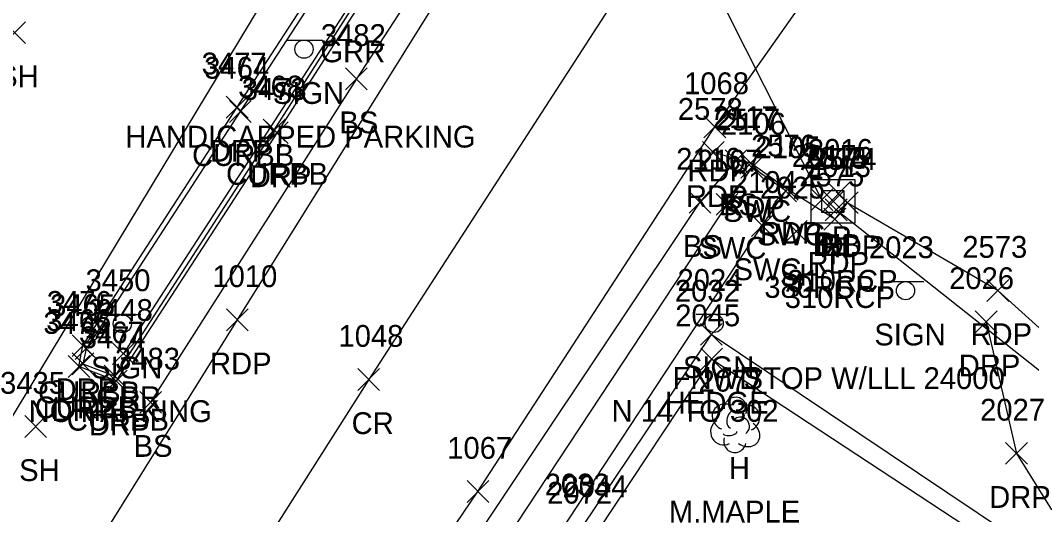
# Model space of a CAD drawing. Extents: x 1634209 to 1639641, y 608564 to 612258.
# Drawn here: x 1639060.6 to 1639153.3, y 611205.4 to 611250.8 of the extents above; entities that cross this region are included whole.
import ezdxf

# ---------------------------------------------------------------- set-up
doc = ezdxf.new("R2010")
doc.units = 0
for name, color, linetype in [('D_A', 7, 'Continuous'), ('D_C', 7, 'Continuous'), ('D_I', 7, 'Continuous'), ('D_TIC', 7, 'Continuous'), ('DCP', 7, 'Continuous'), ('DS', 7, 'Continuous'), ('L_A', 7, 'Continuous'), ('L_C', 7, 'Continuous'), ('L_I', 7, 'Continuous'), ('L_TIC', 7, 'Continuous'), ('LAHR', 7, 'Continuous'), ('LELB', 7, 'Continuous'), ('LFNC', 7, 'Continuous'), ('LTD', 7, 'Continuous'), ('P_A', 7, 'Continuous'), ('P_I', 7, 'Continuous'), ('P_TIC', 7, 'Continuous'), ('PET', 7, 'Continuous'), ('PRC', 7, 'Continuous'), ('R_A', 7, 'Continuous'), ('R_I', 7, 'Continuous'), ('R_TIC', 7, 'Continuous'), ('RC', 7, 'Continuous'), ('RDP', 7, 'Continuous'), ('RGR', 7, 'Continuous'), ('RSW', 7, 'Continuous'), ('S_A', 7, 'Continuous'), ('S_C', 7, 'Continuous'), ('S_I', 7, 'Continuous'), ('SSGN', 7, 'Continuous')]:
    doc.layers.add(name, color=color, linetype=linetype)

msp = doc.modelspace()

# ---------------------------------------------------------------- linework, layer by layer
at = {"layer": 'D_TIC'}
for points in [[(1639134.631, 611233.883), (1639136.631, 611235.883)], [(1639136.631, 611233.883), (1639134.631, 611235.883)], [(1639133.093, 611233.316), (1639135.093, 611235.316)], [(1639135.093, 611233.316), (1639133.093, 611235.316)], [(1639134.136, 611233.162), (1639136.136, 611235.162)], [(1639136.136, 611233.162), (1639134.136, 611235.162)], [(1639134.4, 611232.388), (1639136.4, 611234.388)], [(1639136.4, 611232.388), (1639134.4, 611234.388)]]:
    msp.add_lwpolyline(points, dxfattribs=at)
at = {"layer": 'DCP'}
for points in [[(1639053.212, 611203.404), (1639105.209, 611289.55)], [(1639134.093, 611234.316), (1639106.078, 611289.886)], [(1639159.896, 611213.983), (1639135.4, 611233.388)]]:
    msp.add_lwpolyline(points, dxfattribs=at)
at = {"layer": 'DS'}
for p, q in [((1639133.093, 611236.155), (1639137.093, 611236.155)), ((1639133.093, 611232.155), (1639133.093, 611236.155)), ((1639137.093, 611236.155), (1639137.093, 611232.155)), ((1639134.093, 611233.155), (1639134.093, 611235.155)), ((1639134.093, 611235.155), (1639136.093, 611235.155)), ((1639136.093, 611235.155), (1639136.093, 611233.155)), ((1639135.098, 611234.157), (1639135.098, 611234.157)), ((1639135.098, 611234.157), (1639135.098, 611234.157)), ((1639136.093, 611233.155), (1639134.093, 611233.155)), ((1639137.093, 611232.155), (1639133.093, 611232.155))]:
    msp.add_line(p, q, dxfattribs=at)
at = {"layer": 'L_TIC'}
for points in [[(1639059.097, 611248.624), (1639061.097, 611250.624)], [(1639061.097, 611248.624), (1639059.097, 611250.624)], [(1639090.422, 611244.404), (1639092.422, 611246.404)], [(1639092.422, 611244.404), (1639090.422, 611246.404)], [(1639125.22, 611236.882), (1639127.22, 611238.882)], [(1639127.22, 611236.882), (1639125.22, 611238.882)], [(1639121.911, 611233.067), (1639123.911, 611235.067)], [(1639123.911, 611233.067), (1639121.911, 611235.067)], [(1639130.75, 611230.422), (1639132.75, 611232.422)], [(1639132.75, 611230.422), (1639130.75, 611232.422)], [(1639122.947, 611220.972), (1639124.947, 611222.972)], [(1639124.947, 611220.972), (1639122.947, 611222.972)], [(1639122.989, 611218.711), (1639124.989, 611220.711)], [(1639124.989, 611218.711), (1639122.989, 611220.711)], [(1639071.56, 611214.741), (1639073.56, 611216.741)], [(1639073.56, 611214.741), (1639071.56, 611216.741)], [(1639061.02, 611212.522), (1639063.02, 611214.522)], [(1639063.02, 611212.522), (1639061.02, 611214.522)]]:
    msp.add_lwpolyline(points, dxfattribs=at)
at = {"layer": 'LAHR'}
msp.add_lwpolyline([(1639113.651, 611204.037), (1639123.989, 611219.711), (1639156.206, 611198.515)], dxfattribs=at)
at = {"layer": 'LELB'}
for points in [[(1639113.243, 611281.921), (1639107.569, 611270.212), (1639091.422, 611245.404), (1639072.56, 611215.741)], [(1639041.81, 611107.811), (1639056.236, 611130.355), (1639075.108, 611160.999), (1639098.499, 611197.466), (1639122.911, 611234.067), (1639126.22, 611237.882)]]:
    msp.add_lwpolyline(points, dxfattribs=at)
at = {"layer": 'LFNC'}
msp.add_lwpolyline([(1639155.815, 611192.801), (1639159.249, 611198.276), (1639123.947, 611221.972), (1639112.019, 611204.198)], dxfattribs=at)
at = {"layer": 'LTD'}
msp.add_line((1639126.125, 611213.72), (1639126.125, 611213.72), dxfattribs=at)
msp.add_line((1639126.125, 611213.72), (1639126.125, 611213.72), dxfattribs=at)
msp.add_arc((1639126.172, 611215.154), 1.047, 335.52715, 180.95627, dxfattribs=at)
for centre, major_axis, ratio, start_param, end_param in [((1639125.333, 611214.386), (1.21, -0.512), 0.895232, 1.570796, 4.712389), ((1639127.167, 611214.303), (-1.141, -0.483), 0.949671, 1.570796, 4.712389), ((1639125.917, 611214.178), (-0.208, -0.792), 0.645439, 3.141593, 6.283185), ((1639126.625, 611213.553), (-0.5, 0.667), 0.989748, 3.141593, 6.283185), ((1639125.042, 611213.011), (0.584, -1.042), 0.959034, 3.141593, 6.283185), ((1639127.125, 611212.886), (-1.09, 0.792), 0.841452, 1.570796, 4.712389), ((1639126.125, 611212.22), (0.265, 1.061), 0.942809, 1.570796, 4.712389), ((1639125.667, 611212.969), (-0.625, -0.083), 0.423636, 0, 3.141593)]:
    msp.add_ellipse(centre, major_axis=major_axis, ratio=ratio, start_param=start_param, end_param=end_param, dxfattribs=at)
at = {"layer": 'P_TIC'}
for points in [[(1639123.272, 611239.99), (1639125.272, 611241.99)], [(1639125.272, 611239.99), (1639123.272, 611241.99)], [(1639123.139, 611237.638), (1639125.139, 611239.638)], [(1639125.139, 611237.638), (1639123.139, 611239.638)], [(1639126.562, 611236.663), (1639128.562, 611238.663)], [(1639128.562, 611236.663), (1639126.562, 611238.663)], [(1639129.918, 611234.275), (1639131.918, 611236.275)], [(1639131.918, 611234.275), (1639129.918, 611236.275)], [(1639135.405, 611233.042), (1639137.405, 611235.042)], [(1639137.405, 611233.042), (1639135.405, 611235.042)], [(1639134.28, 611231.533), (1639136.28, 611233.533)], [(1639136.28, 611231.533), (1639134.28, 611233.533)], [(1639149.219, 611224.989), (1639151.219, 611226.989)], [(1639151.219, 611224.989), (1639149.219, 611226.989)], [(1639079.513, 611222.302), (1639081.513, 611224.302)], [(1639081.513, 611222.302), (1639079.513, 611224.302)], [(1639091.552, 611216.828), (1639093.552, 611218.828)], [(1639093.552, 611216.828), (1639091.552, 611218.828)], [(1639101.566, 611206.561), (1639103.566, 611208.561)], [(1639103.566, 611206.561), (1639101.566, 611208.561)]]:
    msp.add_lwpolyline(points, dxfattribs=at)
at = {"layer": 'PET'}
for points in [[(1638854.828, 610853.218), (1638885.372, 610909), (1638902.819, 610937.282), (1638929.331, 610982.561), (1638950.918, 611019.419), (1638971.285, 611051.917), (1639000.041, 611096.961), (1639023.569, 611133.699), (1639039.122, 611159.191), (1639064.624, 611197.785), (1639080.513, 611223.302), (1639114.226, 611277.337), (1639131.174, 611302.276), (1639149.638, 611331.789), (1639176.419, 611372.354), (1639193.482, 611398.877), (1639220.957, 611441.468), (1639247.215, 611483.75)], [(1638878.405, 610839.817), (1638902.262, 610883.101), (1638925.756, 610925.063), (1638957.254, 610978.118), (1638978.727, 611014.117), (1639004.294, 611055.324), (1639040.966, 611112.282), (1639073.406, 611162.89), (1639072.716, 611163.464), (1639102.566, 611207.561), (1639124.272, 611240.99), (1639140.685, 611264.292), (1639156.198, 611287.398), (1639175.63, 611318.102), (1639189.772, 611341.609), (1639219.882, 611389.38), (1639245.262, 611428.037), (1639265.275, 611462.646)], [(1639410.825, 610892.364), (1639390.458, 610919.541), (1639371.801, 610946.358), (1639349.879, 610975.696), (1639327.189, 611005.386), (1639302.754, 611038.38), (1639275.028, 611075.512), (1639248.834, 611108.817), (1639223.626, 611142.441), (1639205.296, 611166.276), (1639182.184, 611194.122), (1639165.678, 611212.038), (1639150.219, 611225.989), (1639136.405, 611234.042), (1639135.28, 611232.533), (1639130.918, 611235.275), (1639127.562, 611237.663), (1639124.139, 611238.638)]]:
    msp.add_lwpolyline(points, dxfattribs=at)
at = {"layer": 'PRC'}
msp.add_lwpolyline([(1639250.459, 611462.838), (1639222.36, 611418.184), (1639195.342, 611376.275), (1639169.71, 611336.75), (1639147.167, 611302.779), (1639120.589, 611261.162), (1639092.552, 611217.828), (1639063.709, 611172.415), (1639032.458, 611123.696), (1639004.791, 611080.304), (1638977.88, 611037.269), (1638950.436, 610992.128), (1638925.956, 610950.29), (1638900.285, 610905.363), (1638879.746, 610869.196), (1638867.145, 610846.082)], dxfattribs=at)
at = {"layer": 'R_TIC'}
for points in [[(1639079.495, 611241.8), (1639081.495, 611243.8)], [(1639081.495, 611241.8), (1639079.495, 611243.8)], [(1639079.778, 611241.409), (1639081.778, 611243.409)], [(1639081.778, 611241.409), (1639079.778, 611243.409)], [(1639082.889, 611239.687), (1639084.889, 611241.687)], [(1639084.889, 611239.687), (1639082.889, 611241.687)], [(1639083.165, 611239.463), (1639085.165, 611241.463)], [(1639085.165, 611239.463), (1639083.165, 611241.463)], [(1639126.669, 611236.284), (1639128.669, 611238.284)], [(1639128.669, 611236.284), (1639126.669, 611238.284)], [(1639129.776, 611234.122), (1639131.776, 611236.122)], [(1639131.776, 611234.122), (1639129.776, 611236.122)], [(1639124.395, 611232.898), (1639126.395, 611234.898)], [(1639126.395, 611232.898), (1639124.395, 611234.898)], [(1639127.622, 611230.936), (1639129.622, 611232.936)], [(1639129.622, 611230.936), (1639127.622, 611232.936)], [(1639148.147, 611222.119), (1639150.147, 611224.119)], [(1639150.147, 611222.119), (1639148.147, 611224.119)], [(1639065.357, 611219.94), (1639067.357, 611221.94)], [(1639067.357, 611219.94), (1639065.357, 611221.94)], [(1639065.652, 611219.653), (1639067.652, 611221.653)], [(1639067.652, 611219.653), (1639065.652, 611221.653)], [(1639069.072, 611219.203), (1639071.072, 611221.203)], [(1639071.072, 611219.203), (1639069.072, 611221.203)], [(1639064.987, 611218.018), (1639066.987, 611220.018)], [(1639066.987, 611218.018), (1639064.987, 611220.018)], [(1639065.359, 611218.274), (1639067.359, 611220.274)], [(1639067.359, 611218.274), (1639065.359, 611220.274)], [(1639068.295, 611217.144), (1639070.295, 611219.144)], [(1639070.295, 611217.144), (1639068.295, 611219.144)], [(1639068.408, 611216.699), (1639070.408, 611218.699)], [(1639070.408, 611216.699), (1639068.408, 611218.699)], [(1639150.93, 611210.062), (1639152.93, 611212.062)], [(1639152.93, 611210.062), (1639150.93, 611212.062)]]:
    msp.add_lwpolyline(points, dxfattribs=at)
at = {"layer": 'RC'}
msp.add_lwpolyline([(1639104.858, 611279.429), (1639092.734, 611260.844), (1639080.778, 611242.409), (1639066.652, 611220.653), (1639066.359, 611219.274), (1639069.295, 611218.144), (1639083.889, 611240.687), (1639098.149, 611263.05), (1639106.115, 611275.731)], dxfattribs=at)
at = {"layer": 'RDP'}
for points in [[(1639106.497, 611275.321), (1639098.464, 611262.727), (1639084.165, 611240.463), (1639069.408, 611217.699), (1639065.987, 611219.018), (1639066.357, 611220.94), (1639080.495, 611242.8), (1639092.355, 611261.077), (1639105.006, 611280.566)], [(1639149.147, 611223.119), (1639151.93, 611211.062), (1639160.002, 611198.081), (1639156.164, 611192.928)]]:
    msp.add_lwpolyline(points, dxfattribs=at)
at = {"layer": 'RGR'}
msp.add_lwpolyline([(1639105.677, 611275.426), (1639090.632, 611251.917), (1639070.072, 611220.203)], dxfattribs=at)
at = {"layer": 'RSW'}
msp.add_lwpolyline([(1639046.008, 611105.024), (1639061.85, 611129.552), (1639078.572, 611155.899), (1639101.994, 611191.521), (1639128.622, 611231.936), (1639130.776, 611235.122), (1639127.669, 611237.284), (1639125.395, 611233.898), (1639098.324, 611192.857), (1639074.538, 611156.78), (1639058.008, 611130.674), (1639042.924, 611107.097)], dxfattribs=at)
at = {"layer": 'SSGN'}
for p, q in [((1639084.971, 611248.952), (1639088.305, 611248.952)), ((1639086.618, 611248.119), (1639086.618, 611248.119)), ((1639140.111, 611226.808), (1639143.445, 611226.808)), ((1639141.758, 611225.975), (1639141.758, 611225.975)), ((1639068.316, 611223.783), (1639071.649, 611223.783)), ((1639122.567, 611223.814), (1639125.9, 611223.814)), ((1639069.963, 611222.95), (1639069.963, 611222.95)), ((1639124.213, 611222.98), (1639124.213, 611222.98))]:
    msp.add_line(p, q, dxfattribs=at)
for centre in [(1639086.618, 611248.119), (1639141.758, 611225.975), (1639069.963, 611222.95), (1639124.213, 611222.98)]:
    msp.add_circle(centre, 0.833, dxfattribs=at)

# ---------------------------------------------------------------- texts
at = {"layer": 'D_A'}
for s, p in [('P', (1639135.009, 611229.883)), ('DIB', (1639133.238, 611229.162)), ('P', (1639133.471, 611229.316)), ('DI', (1639134.153, 611229.157)), ('P', (1639134.778, 611228.388))]:
    msp.add_text(s, height=2, dxfattribs=at).set_placement(p)
at = {"layer": 'D_C'}
for s, p in [('380RCP', (1639128.809, 611225.316)), ('310RCP', (1639130.915, 611225.883)), ('310RCP', (1639130.684, 611224.388))]:
    msp.add_text(s, height=2, dxfattribs=at).set_placement(p)
at = {"layer": 'D_I'}
for s, p in [('2017', (1639131.321, 611237.316)), ('2016', (1639132.805, 611237.883)), ('2015', (1639132.326, 611237.157)), ('2014', (1639132.364, 611237.162)), ('2013', (1639132.628, 611236.388))]:
    msp.add_text(s, height=2, dxfattribs=at).set_placement(p)
at = {"layer": 'L_A'}
for s, p in [('SH', (1639058.585, 611244.624)), ('BS', (1639089.863, 611240.404)), ('BS', (1639124.661, 611232.882)), ('BS', (1639121.352, 611229.067)), ('SH', (1639130.239, 611226.422)), ('FNWD', (1639120.412, 611216.972)), ('HEDGE', (1639119.69, 611214.711)), ('BS', (1639071.001, 611210.741)), ('SH', (1639060.508, 611208.522)), ('H', (1639125.558, 611208.72))]:
    msp.add_text(s, height=2, dxfattribs=at).set_placement(p)
at = {"layer": 'L_C'}
msp.add_text('M.MAPLE', height=2, dxfattribs=at).set_placement((1639120.062, 611204.72))
at = {"layer": 'L_I'}
for s, p in [('3482', (1639088.162, 611248.404)), ('2117', (1639124.094, 611240.882)), ('2116', (1639120.731, 611237.067)), ('2025', (1639128.412, 611234.422)), ('2032', (1639120.609, 611224.972)), ('2045', (1639120.65, 611222.711)), ('3483', (1639069.3, 611218.741)), ('3435', (1639058.76, 611216.522)), ('2077', (1639122.787, 611216.72)), ('2033', (1639108.681, 611207.198)), ('2044', (1639110.312, 611207.037))]:
    msp.add_text(s, height=2, dxfattribs=at).set_placement(p)
at = {"layer": 'P_A'}
for s, p in [('RDP', (1639121.76, 611235.99)), ('RDP', (1639121.627, 611233.638)), ('RDP', (1639125.05, 611232.663)), ('RDP', (1639128.406, 611230.275)), ('RDP', (1639133.893, 611229.042)), ('RDP', (1639132.768, 611227.533)), ('RDP', (1639147.707, 611220.989)), ('RDP', (1639078.002, 611218.302)), ('CR', (1639090.985, 611212.828))]:
    msp.add_text(s, height=2, dxfattribs=at).set_placement(p)
at = {"layer": 'P_I'}
for s, p in [('1068', (1639121.453, 611243.99)), ('2578', (1639120.88, 611241.638)), ('2577', (1639124.302, 611240.663)), ('2576', (1639127.603, 611238.275)), ('2574', (1639133.145, 611237.042)), ('2575', (1639132.02, 611235.533)), ('2573', (1639146.959, 611228.989)), ('1010', (1639078.222, 611226.302)), ('1048', (1639089.78, 611220.828)), ('1067', (1639099.747, 611210.561))]:
    msp.add_text(s, height=2, dxfattribs=at).set_placement(p)
at = {"layer": 'R_A'}
for s, p in [('GRR', (1639088.12, 611246.917)), ('CURBB', (1639076.361, 611237.409)), ('DRP', (1639077.983, 611237.8)), ('CURBB', (1639079.471, 611235.687)), ('DRP', (1639081.653, 611235.463)), ('SWC', (1639125.032, 611232.284)), ('SWC', (1639128.139, 611230.122)), ('SWC', (1639122.757, 611228.898)), ('SWC', (1639125.985, 611226.936)), ('DRP', (1639146.635, 611218.119)), ('DRP', (1639063.845, 611215.94)), ('CURBB', (1639062.235, 611215.653)), ('GRR', (1639067.56, 611215.203)), ('CURBB', (1639061.941, 611214.274)), ('DRP', (1639063.475, 611214.018)), ('CURBB', (1639064.878, 611213.144)), ('DRP', (1639066.896, 611212.699)), ('DRP', (1639149.418, 611206.062))]:
    msp.add_text(s, height=2, dxfattribs=at).set_placement(p)
at = {"layer": 'R_I'}
for s, p in [('3477', (1639077.235, 611245.8)), ('3464', (1639077.471, 611245.409)), ('3468', (1639080.582, 611243.687)), ('3473', (1639080.905, 611243.463)), ('2106', (1639124.843, 611240.284)), ('2105', (1639128.005, 611238.122)), ('2107', (1639122.623, 611236.898)), ('2104', (1639125.851, 611234.936)), ('2026', (1639145.753, 611226.119)), ('3476', (1639063.042, 611223.94)), ('3465', (1639063.345, 611223.653)), ('3448', (1639066.812, 611223.203)), ('3475', (1639062.728, 611222.018)), ('3466', (1639062.997, 611222.274)), ('3467', (1639065.988, 611221.144)), ('3474', (1639066.148, 611220.699)), ('2027', (1639148.591, 611214.062)), ('2072', (1639108.912, 611206.452))]:
    msp.add_text(s, height=2, dxfattribs=at).set_placement(p)
at = {"layer": 'S_A'}
for p in [(1639083.756, 611243.098), (1639138.896, 611220.955), (1639067.101, 611217.93), (1639121.351, 611217.96)]:
    msp.add_text('SIGN', height=2, dxfattribs=at).set_placement(p)
at = {"layer": 'S_C'}
for s, p in [('HANDICAPPED PARKING', (1639070.245, 611239.098)), ('STOP W/LLL 24000', (1639126.912, 611216.955)), ('NO PARKING', (1639061.384, 611213.93)), ('N 14 TO 302', (1639114.808, 611213.96))]:
    msp.add_text(s, height=2, dxfattribs=at).set_placement(p)
at = {"layer": 'S_I'}
for s, p in [('2023', (1639138.4, 611228.955)), ('3450', (1639066.597, 611225.93)), ('2024', (1639120.855, 611225.96))]:
    msp.add_text(s, height=2, dxfattribs=at).set_placement(p)

doc.saveas('drawing.dxf')
